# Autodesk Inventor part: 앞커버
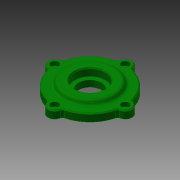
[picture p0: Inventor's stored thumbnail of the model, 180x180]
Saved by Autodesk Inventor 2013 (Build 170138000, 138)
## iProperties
Company: 한국ATC센터
Created: 2015-12
Part Number: 앞커버
Document SubType Name: Modeling
Designer: mdu
Density: 1 g/cm^3
Material: 일반
Author: mdu
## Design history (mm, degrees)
sketch "스케치1"
  geometry: C1 r 1.621 at (0, 6.75) reference; C2 r 1.621 at (-37, -30.25) reference; C3 r 1.621 at (0, -67.25) reference; C4 r 1.621 at (37, -30.25) reference; C5 r 10 at (0, -30.25) reference; C6 r 12 at (0, -30.25); C7 r 24.5 at (0, -30.25) reference; A1 r 3 centre (-38.77, -20.408) between (-38.239, -23.361) and (-35.862, -21.146) reference; A2 r 7 centre (-37, -30.25) between (-38.239, -23.361) and (-38.239, -37.139) reference; A3 r 3 centre (-38.77, -40.092) between (-35.862, -39.354) and (-38.239, -37.139) reference; A4 r 37 centre (0, -30.25) between (-35.862, -39.354) and (-9.104, -66.113) reference; A5 r 3 centre (-9.842, -69.02) between (-6.889, -68.489) and (-9.104, -66.113) reference; A6 r 7 centre (0, -67.25) between (-6.889, -68.489) and (6.889, -68.489) reference; A7 r 3 centre (9.842, -69.02) between (9.104, -66.112) and (6.889, -68.489) reference; A8 r 37 centre (0, -30.25) between (9.104, -66.112) and (35.863, -39.354) reference; A9 r 3 centre (38.77, -40.092) between (38.239, -37.139) and (35.863, -39.354) reference; A10 r 7 centre (37, -30.25) between (38.239, -37.139) and (38.239, -23.361) reference; A11 r 3 centre (38.77, -20.408) between (35.863, -21.146) and (38.239, -23.361) reference; A12 r 37 centre (0, -30.25) between (35.863, -21.146) and (9.104, 5.612) reference; A13 r 3 centre (9.842, 8.52) between (6.889, 7.989) and (9.104, 5.612) reference; A14 r 7 centre (0, 6.75) between (6.889, 7.989) and (-6.889, 7.989) reference; A15 r 3 centre (-9.842, 8.52) between (-9.104, 5.612) and (-6.889, 7.989) reference; A16 r 37 centre (0, -30.25) between (-9.104, 5.612) and (-35.862, -21.146) reference; 1 further point
  constraints: 1 centre point, 1 coincident
  dimensions: "d2" = 2 radial gap between concentric circles of C6 C5
extrude "돌출1" new body sketch "스케치1" distance "d0" = 8; taper "d1" = 0 deg
sketch "스케치2"
  geometry: C1 r 23.5 at (0, -30.25) reference; C2 r 12 at (0, -30.25) reference; 1 further point
extrude "돌출2" join sketch "스케치2" distance "d4" = 6; taper "d5" = 0 deg
sketch "스케치9"
  geometry: C1 r 21 at (0, 0); C2 r 23.5 at (0, 0) reference; 1 further point
  constraints: 1 centre point, 1 coincident
  dimensions: "d60" = 42 diameter of C1
extrude "돌출6" cut sketch "스케치9" distance "d63" = 3; taper "d64" = 0 deg
node "작업 평면1"
sketch "스케치4"
  geometry: C1 r 12 at (0, -30.25) reference; C2 r 27 at (0, -30.25); 1 further point
  constraints: 1 centre point
  dimensions: "d10" = 15 radial gap between concentric circles of C1 C2
extrude "돌출4" join sketch "스케치4" distance "d11" = 4; taper "d12" = -20 deg
fillet "모깎기2" dims "d13" = 3
node "작업점1"
  node "작업축1"
chamfer "모따기2" distance "d24" = 1; stored, may be unused: second distance "d25" = 2, angle "d26" = 45 deg
hole "구멍6" diameter "d43" = 4.5; stored, may be unused: countersink angle "d47" = 90 deg, drill point angle "d49" = 118 deg; dims "d41" = 10, "d42" = 10, "d44" = 6, "d45" = 8, "d46" = 4.4, "d48" = 8
sketch "스케치8"
  geometry: C1 r 13.456 at (0, 0) reference; C2 r 16 at (0, 0); 1 further point
  constraints: 1 centre point, 1 coincident
  dimensions: "d53" = 32 diameter of C2
extrude "돌출5" cut sketch "스케치8" distance "d54" = 8.3; taper "d55" = 0 deg
fillet "모깎기3" dims "d56" = 0.3
chamfer "모따기3" distance "d57" = 1.2; stored, may be unused: second distance "d58" = 2, angle "d59" = 30 deg
node "솔리드1"
pattern_circular "원형 패턴1" dims angle "d51" = 360 deg
node "참조1"
node "참조2"
